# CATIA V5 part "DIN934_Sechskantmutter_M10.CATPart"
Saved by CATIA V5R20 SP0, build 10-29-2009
Part number: DIN934_Sechskantmutter_M10
Bounding box of the stored display mesh (mm): x -9.815 to 9.815, y -8.5 to 8.5, z -4 to 4
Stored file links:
  C:\Users\Andi\Desktop\Plasma\DIN934_Sechskantmutter_M10.CATPart
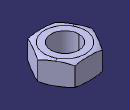
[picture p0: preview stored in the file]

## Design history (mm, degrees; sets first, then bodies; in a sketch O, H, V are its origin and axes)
AxisSystem1: origin (0, 0, 0), X (1, 0, 0), Y (0, 1, 0), Z (0, 0, 1)
Body1 (main body)
  Sketch1 on XY plane of AxisSystem1, origin (0, 0, 0), H (1, 0, 0), V (0, 1, 0)
    point P1 (9.815, 0)
    point P2 (4.9075, 8.5)
    point P3 (-4.9075, 8.5)
    point P4 (-9.815, 0)
    point P5 (-4.9075, -8.5)
    point P6 (4.9075, -8.5)
    point P7 (7.3612, 4.25)
    line L1 (9.815, 0) -> (4.9075, 8.5)
    line L2 (4.9075, 8.5) -> (-4.9075, 8.5)
    line L3 (-4.9075, 8.5) -> (-9.815, 0)
    line L4 (-9.815, 0) -> (-4.9075, -8.5)
    line L5 (-4.9075, -8.5) -> (4.9075, -8.5)
    line L6 (4.9075, -8.5) -> (9.815, 0)
    construction line L7 (0, 0) -> (7.3612, 4.25)
    construction circle A1 centre (0, 0) radius 9.815
    construction arc A2 centre (-4.9075, -8.5) radius 9.815 from (-9.815, 0) to (4.9075, -8.5) cw
    construction arc A3 centre (4.9075, 8.5) radius 9.815 from (-4.9075, 8.5) to (9.815, 0) ccw
    circle A4 centre (0, 0) radius 5
    distance L1 L4 = 17
    radius A4 = 5
    coincidence: A1 P1, A1 P2, A1 P3, A1 P4, A1 P5, A1 P6, A2 O, A3 O
    midpoint: P7 L1
    horizontal: L2 H
  Pad1: profile Sketch1, direction (0, 0, 1), length 4, mirrored extent
  Sketch2 on ZX plane of AxisSystem1, origin (0, 0, 0), H (0, 0, 1), V (1, 0, 0)
    arc A1 centre (-0.8143, 7.315) radius 4.8143 from (4, 7.315) to (3.3, 9.815) ccw
    line L1 (3.3, 9.815) -> (4, 9.815)
    line L2 (4, 9.815) -> (4, 7.315)
    reference projected line E1 (-4, 9.815) -> (4, 9.815) from edge [face of Pad1 from Sketch1.L1 | face of Pad1 from Sketch1.L6]
    reference intersected line E2 through (4, 0) direction (0, 1) from end face of Pad1
    length L1 = 0.7
    length L2 = 2.5
    vertical: L2 V
    horizontal: L1 H
    tangency: A1 L2
    coincidence: L1 E1, E2 L2
  Groove1: profile Sketch2, axis axis of face of Pad1 from Sketch1.A4, angle 360
  Mirror1: of Groove1, about XY plane of AxisSystem1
